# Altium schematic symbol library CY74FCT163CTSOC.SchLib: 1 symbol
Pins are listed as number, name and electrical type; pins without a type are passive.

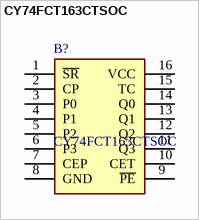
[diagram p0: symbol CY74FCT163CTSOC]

## CY74FCT163CTSOC
designator B?
Counter ICs Synch 4B Bin Counter; Manufacturer_Name: Texas Instruments; Geometry.Height: 2.65mm
footprint SOIC127P1030X265-16N
pins: 1 ~{SR}, 2 CP, 3 P0, 4 P1, 5 P2, 6 P3, 7 CEP, 8 GND, 9 ~{PE}, 10 CET, 11 Q3, 12 Q2, 13 Q1, 14 Q0, 15 TC, 16 VCC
